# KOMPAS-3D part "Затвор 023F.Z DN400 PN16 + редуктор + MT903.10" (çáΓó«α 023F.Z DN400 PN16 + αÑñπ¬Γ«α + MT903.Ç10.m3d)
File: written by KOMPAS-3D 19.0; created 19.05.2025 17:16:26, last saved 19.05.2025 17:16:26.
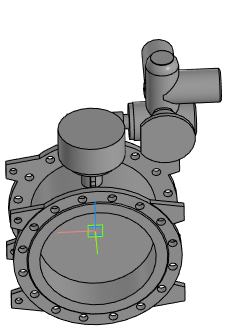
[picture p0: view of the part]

Document properties: Полное имя файла: Затвор 023F.Z DN400 PN16 + редуктор + MT903.10.a3d

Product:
- Part/product: Затвор 023F.Z DN400 PN16 + редуктор + MT903.10
    Масса: 275.761

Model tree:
1. Операция без истории:1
